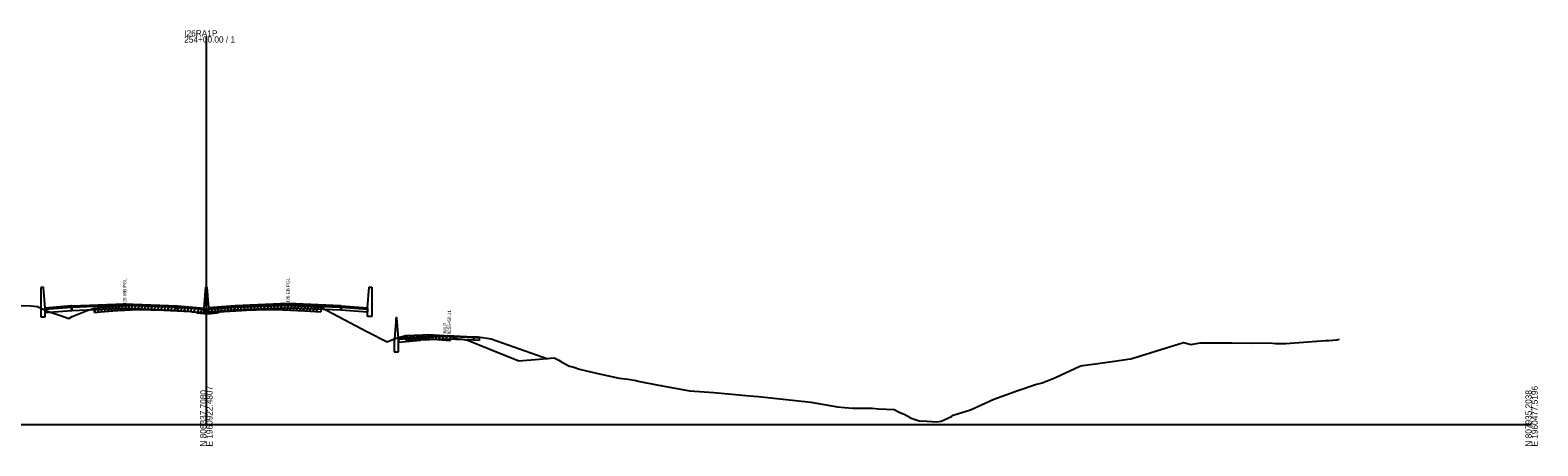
# Model space of a CAD drawing. Extents: x 1017 to 19997, y -1947 to 50737.
# Drawn here: x 10520 to 11203, y 3990 to 4179 of the extents above; entities that cross this region are included whole.
import ezdxf

# ---------------------------------------------------------------- set-up
doc = ezdxf.new("R2010")
doc.units = 0
for name, color, linetype in [('RD_GPK_XS_Cell', 7, 'Continuous'), ('RD_XS_Base', 7, 'Continuous'), ('RD_XS_ExGround', 7, 'Continuous'), ('RD_XS_ExPaveRet', 7, 'Continuous'), ('RD_XS_Greenside', 7, 'Continuous'), ('RD_XS_MedBWall', 7, 'Continuous'), ('RD_XS_Pave', 7, 'Continuous'), ('RD_XS_PaveOvlay', 7, 'Continuous'), ('RD_XS_TX_Notes', 7, 'Continuous')]:
    doc.layers.add(name, color=color, linetype=linetype)

msp = doc.modelspace()

# ---------------------------------------------------------------- linework, layer by layer
at = {"layer": 'RD_GPK_XS_Cell'}
for p, q in [((10600, 4000), (10600, 4175.88)), ((10000, 4000), (10600, 4000)), ((10600, 4000), (11200, 4000))]:
    msp.add_line(p, q, dxfattribs=at)
at = {"layer": 'RD_XS_Base'}
for points in [[(10539, 4053.04), (10527, 4052.08)], [(10527, 4052.08), (10527, 4050.74)], [(10527, 4050.74), (10539, 4051.7)], [(10539, 4051.7), (10539, 4053.04)], [(10539.05, 4051.71), (10539, 4051.7)], [(10539.05, 4053.05), (10539.05, 4051.71)], [(10539.05, 4051.71), (10563, 4052.68), (10587, 4051.71)], [(10587, 4051.71), (10587, 4053.05)], [(10599, 4052.11), (10587, 4053.05)], [(10587, 4051.71), (10599, 4050.77)], [(10599, 4050.77), (10599, 4052.11)], [(10601, 4050.88), (10601, 4052.22)], [(10613, 4051.82), (10601, 4050.88)], [(10613, 4051.82), (10613, 4053.16)], [(10660.95, 4051.83), (10637, 4052.79), (10613, 4051.82)], [(10660.95, 4051.83), (10660.95, 4053.17)], [(10661, 4051.82), (10660.95, 4051.83)], [(10661, 4053.16), (10661, 4051.82)], [(10661, 4053.16), (10673, 4052.2)], [(10661, 4051.82), (10661, 4053.16)], [(10673, 4050.86), (10661, 4051.82)], [(10673, 4052.2), (10673, 4050.86)], [(10697, 4039.48), (10687, 4038.68)], [(10687, 4038.68), (10687, 4037.34)], [(10687, 4037.34), (10697, 4038.14)], [(10697, 4039.48), (10709, 4039.96), (10721, 4039.48)], [(10697, 4038.14), (10697, 4039.48)], [(10721, 4038.16), (10709, 4038.62), (10697, 4038.14)], [(10721, 4039.48), (10721, 4038.16)], [(10721, 4039.48), (10723, 4039.4), (10723.5, 4039.38)], [(10723.5, 4038.04), (10721, 4038.16)], [(10723.5, 4039.38), (10723.5, 4038.04)]]:
    msp.add_lwpolyline(points, dxfattribs=at)
at = {"layer": 'RD_XS_ExGround'}
msp.add_lwpolyline([(10515.4, 4053.93), (10520.5, 4053.83), (10523.6, 4053.52), (10527.64, 4051.47), (10534.02, 4049.33), (10537.67, 4048.06), (10539.3, 4048.88), (10546.11, 4051.59), (10549.36, 4052.76), (10552.01, 4052.98), (10557.64, 4053.45), (10559.86, 4053.59), (10569.02, 4054.15), (10580.8, 4053.74), (10592.78, 4053.15), (10593.54, 4053.05), (10595.51, 4052.87), (10595.7, 4052.56), (10598.98, 4052.34), (10600, 4052.33), (10601.67, 4052.33), (10601.98, 4052.37), (10604.68, 4052.67), (10604.74, 4052.68), (10605.47, 4052.73), (10605.66, 4052.92), (10606.25, 4052.99), (10608.05, 4053.2), (10615.85, 4053.66), (10620.2, 4053.92), (10622.51, 4053.97), (10632.05, 4054.15), (10634.79, 4054.03), (10644.61, 4053.58), (10649.36, 4053.27), (10651.77, 4053.11), (10672.9, 4042), (10681.81, 4037.44), (10685.5, 4038.94), (10690.22, 4040.34), (10697.97, 4040.61), (10700.45, 4040.82), (10702.82, 4040.64), (10710.44, 4040.11), (10712.88, 4039.08), (10714.19, 4038.78), (10715.7, 4038.6), (10717.39, 4038.41), (10717.96, 4038.29), (10728.41, 4034.08), (10741.46, 4028.82), (10750.68, 4029.61), (10757.55, 4030.2), (10759.52, 4029.14), (10761.22, 4028.13), (10764.39, 4026.46), (10765.88, 4026.08), (10768.89, 4025.04), (10777.28, 4023.06), (10786.85, 4020.96), (10791.02, 4020.5), (10794.66, 4019.87), (10795.58, 4019.7), (10804.67, 4017.86), (10805.86, 4017.63), (10806.41, 4017.53), (10818.96, 4015.29), (10829.73, 4014.49), (10846.07, 4013.03), (10847.94, 4012.89), (10850, 4012.71), (10873.7, 4010.14), (10885.75, 4008.05), (10888.88, 4007.67), (10892.77, 4007.42), (10897.72, 4007.45), (10901.38, 4007.34), (10904.29, 4007.16), (10911.4, 4006.86), (10913.65, 4005.58), (10916.21, 4004.5), (10917.65, 4003.73), (10918.25, 4003.35), (10918.71, 4003.09), (10919.04, 4002.93), (10922.77, 4001.72), (10926.23, 4001.44), (10930.74, 4001.13), (10932.7, 4001.52), (10934.09, 4002.15), (10937.36, 4003.63), (10938.07, 4004.25), (10945.93, 4006.63), (10956.5, 4011.55), (10967.43, 4015.43), (10975.45, 4018.05), (10978.42, 4018.87), (10984.44, 4021.27), (10995.48, 4026.49), (10995.87, 4026.51), (10996.66, 4026.7), (11002.62, 4027.5), (11013.34, 4029.05), (11017.19, 4029.59), (11018.63, 4029.75), (11036.11, 4035.24), (11042.39, 4037.22), (11045.95, 4036.28), (11049.1, 4036.89), (11050.32, 4037.06), (11054.1, 4036.99), (11064.35, 4036.94), (11073.82, 4036.88), (11081.56, 4036.93), (11084.09, 4036.64), (11088.78, 4036.76), (11106.77, 4037.99), (11108.14, 4038.06), (11111.77, 4038.4), (11112.99, 4038.66)], dxfattribs=at)
at = {"layer": 'RD_XS_ExPaveRet'}
for p, q in [((10549.36, 4050.76), (10550.4, 4052.85)), ((10549.36, 4050.76), (10549.36, 4052.76)), ((10549.36, 4050.76), (10552.01, 4050.98)), ((10550.86, 4050.89), (10551.9, 4052.97)), ((10552.01, 4050.98), (10557.64, 4051.45)), ((10552.36, 4051.01), (10553.4, 4053.1)), ((10553.86, 4051.14), (10554.9, 4053.22)), ((10555.36, 4051.26), (10556.4, 4053.35)), ((10556.86, 4051.39), (10557.9, 4053.47)), ((10557.64, 4051.45), (10559.86, 4051.59)), ((10558.36, 4051.5), (10559.39, 4053.56)), ((10559.86, 4051.59), (10560.89, 4053.65)), ((10559.86, 4051.59), (10569.02, 4052.15)), ((10561.36, 4051.68), (10562.39, 4053.75)), ((10562.86, 4051.77), (10563.89, 4053.84)), ((10564.36, 4051.87), (10565.39, 4053.93)), ((10565.86, 4051.96), (10566.89, 4054.02)), ((10567.36, 4052.05), (10568.39, 4054.11)), ((10568.86, 4052.14), (10569.85, 4054.12)), ((10569.02, 4052.15), (10580.8, 4051.74)), ((10570.36, 4052.1), (10571.34, 4054.07)), ((10571.86, 4052.05), (10572.84, 4054.02)), ((10573.36, 4052), (10574.34, 4053.96)), ((10574.86, 4051.95), (10575.84, 4053.91)), ((10576.36, 4051.89), (10577.34, 4053.86)), ((10577.86, 4051.84), (10578.84, 4053.81)), ((10579.36, 4051.79), (10580.34, 4053.76)), ((10580.8, 4051.74), (10592.78, 4051.15)), ((10580.86, 4051.74), (10581.83, 4053.69)), ((10582.36, 4051.66), (10583.33, 4053.61)), ((10583.86, 4051.59), (10584.83, 4053.54)), ((10585.36, 4051.52), (10586.33, 4053.47)), ((10586.86, 4051.44), (10587.83, 4053.39)), ((10588.36, 4051.37), (10589.33, 4053.32)), ((10589.86, 4051.29), (10590.83, 4053.25)), ((10591.36, 4051.22), (10592.33, 4053.17)), ((10592.78, 4051.15), (10593.54, 4051.05)), ((10592.86, 4051.14), (10593.8, 4053.03)), ((10593.54, 4051.05), (10595.51, 4050.87)), ((10594.36, 4050.98), (10595.31, 4052.89)), ((10595.51, 4050.87), (10595.7, 4050.56)), ((10595.7, 4050.56), (10598.98, 4050.34)), ((10595.86, 4050.55), (10596.82, 4052.48)), ((10597.36, 4050.45), (10598.32, 4052.38)), ((10598.86, 4050.35), (10599.85, 4052.33)), ((10598.98, 4050.34), (10600, 4050.33)), ((10600, 4050.33), (10601.67, 4050.33)), ((10600.36, 4050.33), (10601.36, 4052.33)), ((10601.67, 4050.33), (10601.98, 4050.37)), ((10601.86, 4050.35), (10602.92, 4052.47)), ((10601.98, 4050.37), (10604.68, 4050.67)), ((10603.36, 4050.52), (10604.42, 4052.64)), ((10604.74, 4050.68), (10605.47, 4050.73)), ((10604.86, 4050.69), (10605.99, 4052.96)), ((10605.47, 4050.73), (10605.66, 4050.92)), ((10605.66, 4050.92), (10606.25, 4050.99)), ((10606.25, 4050.99), (10608.05, 4051.2)), ((10606.36, 4051), (10607.42, 4053.13)), ((10607.86, 4051.18), (10608.89, 4053.25)), ((10608.05, 4051.2), (10615.85, 4051.66)), ((10609.36, 4051.28), (10610.39, 4053.34)), ((10610.86, 4051.37), (10611.89, 4053.43)), ((10612.36, 4051.45), (10613.39, 4053.52)), ((10613.86, 4051.54), (10614.89, 4053.6)), ((10615.36, 4051.63), (10616.39, 4053.69)), ((10615.85, 4051.66), (10620.2, 4051.92)), ((10616.86, 4051.72), (10617.89, 4053.78)), ((10618.36, 4051.81), (10619.39, 4053.88)), ((10619.86, 4051.9), (10620.87, 4053.94)), ((10620.2, 4051.92), (10622.51, 4051.97)), ((10621.36, 4051.95), (10622.37, 4053.97)), ((10622.51, 4051.97), (10632.05, 4052.15)), ((10622.86, 4051.98), (10623.87, 4054)), ((10624.36, 4052.01), (10625.37, 4054.03)), ((10625.86, 4052.04), (10626.87, 4054.05)), ((10627.36, 4052.06), (10628.37, 4054.08)), ((10628.86, 4052.09), (10629.87, 4054.11)), ((10630.36, 4052.12), (10631.37, 4054.14)), ((10631.86, 4052.15), (10632.84, 4054.12)), ((10632.05, 4052.15), (10634.79, 4052.03)), ((10633.36, 4052.09), (10634.33, 4054.05)), ((10634.79, 4052.03), (10644.61, 4051.58)), ((10634.86, 4052.03), (10635.83, 4053.98)), ((10636.36, 4051.96), (10637.33, 4053.91)), ((10637.86, 4051.89), (10638.83, 4053.84)), ((10639.36, 4051.82), (10640.33, 4053.77)), ((10640.86, 4051.75), (10641.83, 4053.71)), ((10642.36, 4051.68), (10643.33, 4053.64)), ((10643.86, 4051.61), (10644.83, 4053.56)), ((10644.61, 4051.58), (10649.36, 4051.27)), ((10645.36, 4051.53), (10646.32, 4053.47)), ((10646.86, 4051.43), (10647.82, 4053.37)), ((10648.36, 4051.33), (10649.32, 4053.27)), ((10649.36, 4051.27), (10651.77, 4051.11)), ((10649.86, 4051.23), (10650.82, 4053.17)), ((10651.77, 4053.11), (10651.77, 4051.11)), ((10690.22, 4038.34), (10691.24, 4040.38)), ((10690.22, 4038.34), (10690.22, 4040.34)), ((10690.22, 4038.34), (10697.97, 4038.61)), ((10691.72, 4038.39), (10692.74, 4040.43)), ((10693.22, 4038.45), (10694.24, 4040.48)), ((10694.72, 4038.5), (10695.74, 4040.53)), ((10696.22, 4038.55), (10697.24, 4040.58)), ((10697.72, 4038.6), (10698.75, 4040.68)), ((10697.97, 4038.61), (10700.45, 4038.82)), ((10699.22, 4038.71), (10700.26, 4040.8)), ((10700.45, 4038.82), (10702.82, 4038.64)), ((10700.72, 4038.8), (10701.68, 4040.73)), ((10702.22, 4038.69), (10703.18, 4040.62)), ((10702.82, 4038.64), (10710.44, 4038.11)), ((10703.72, 4038.58), (10704.68, 4040.51)), ((10705.22, 4038.47), (10706.18, 4040.41)), ((10706.72, 4038.37), (10707.68, 4040.3)), ((10708.22, 4038.26), (10709.18, 4040.2)), ((10710.44, 4040.11), (10710.44, 4038.11))]:
    msp.add_line(p, q, dxfattribs=at)
at = {"layer": 'RD_XS_Greenside'}
for points in [[(10723, 4039.71), (10729, 4038.75)], [(10729, 4038.75), (10754.67, 4029.74)]]:
    msp.add_lwpolyline(points, dxfattribs=at)
at = {"layer": 'RD_XS_MedBWall'}
for points in [[(10527, 4052.76), (10526.25, 4062.1), (10525, 4062.1)], [(10525, 4062.1), (10525, 4048.76)], [(10599, 4052.76), (10599.75, 4062.22), (10600.25, 4062.22), (10601, 4052.88)], [(10673, 4052.88), (10673.75, 4062.22), (10675, 4062.22)], [(10675, 4062.22), (10675, 4048.88)], [(10525, 4048.76), (10527, 4048.76)], [(10527, 4048.76), (10527, 4052.76)], [(10599, 4050.76), (10599, 4052.76)], [(10601, 4050.76), (10599, 4050.76)], [(10601, 4052.88), (10601, 4050.76)], [(10673, 4048.88), (10673, 4052.88)], [(10675, 4048.88), (10673, 4048.88)], [(10687, 4038.99), (10686.25, 4048.33), (10685.75, 4048.33)], [(10685.75, 4048.33), (10685.75, 4046.33)], [(10685.75, 4046.33), (10685, 4036.99)], [(10685, 4036.99), (10685, 4032.99)], [(10687, 4032.99), (10687, 4038.99)], [(10685, 4032.99), (10687, 4032.99)]]:
    msp.add_lwpolyline(points, dxfattribs=at)
at = {"layer": 'RD_XS_Pave'}
for points in [[(10539, 4053.38), (10527, 4052.42)], [(10527, 4052.42), (10527, 4052.08)], [(10539, 4053.04), (10539, 4053.38)], [(10539.05, 4053.05), (10539, 4053.04)], [(10539.05, 4053.39), (10563, 4054.35), (10587, 4053.39)], [(10587, 4053.05), (10563, 4054.02), (10539.05, 4053.05)], [(10539.05, 4053.05), (10539.05, 4053.39)], [(10587, 4053.39), (10587, 4053.05)], [(10587, 4053.39), (10599, 4052.45)], [(10599, 4052.45), (10599, 4052.11)], [(10613, 4053.5), (10601, 4052.56)], [(10601, 4052.22), (10613, 4053.16)], [(10601, 4052.56), (10601, 4052.22)], [(10660.95, 4053.51), (10637, 4054.46), (10613, 4053.5)], [(10613, 4053.16), (10637, 4054.13), (10660.95, 4053.17)], [(10613, 4053.5), (10613, 4053.16)], [(10660.95, 4053.17), (10660.95, 4053.51)], [(10660.95, 4053.51), (10661, 4053.5)], [(10661, 4053.16), (10660.95, 4053.17)], [(10661, 4053.5), (10661, 4053.16)], [(10661, 4053.16), (10661, 4053.5)], [(10673, 4052.54), (10673, 4052.2)]]:
    msp.add_lwpolyline(points, dxfattribs=at)
at = {"layer": 'RD_XS_PaveOvlay'}
for points in [[(10660.95, 4053.84), (10637, 4054.8), (10613, 4053.84)], [(10539, 4053.72), (10527, 4052.76)], [(10527, 4052.76), (10527, 4052.42)], [(10539.05, 4053.73), (10539, 4053.72)], [(10539, 4053.72), (10539, 4053.38)], [(10539, 4053.38), (10539.05, 4053.39)], [(10539.05, 4053.73), (10563, 4054.68), (10587, 4053.72)], [(10539.05, 4053.39), (10539.05, 4053.73)], [(10587, 4053.72), (10587, 4053.39)], [(10587, 4053.72), (10599, 4052.76)], [(10599, 4052.76), (10599, 4052.45)], [(10613, 4053.84), (10601, 4052.88)], [(10601, 4052.88), (10601, 4052.56)], [(10613, 4053.84), (10613, 4053.5)], [(10660.95, 4053.51), (10660.95, 4053.84)], [(10660.95, 4053.84), (10661, 4053.84)], [(10661, 4053.84), (10661, 4053.5)], [(10661, 4053.84), (10673, 4052.88)], [(10661, 4053.5), (10661, 4053.84)], [(10673, 4052.54), (10661, 4053.5)], [(10673, 4052.88), (10673, 4052.54)], [(10697, 4039.79), (10687, 4038.99)], [(10687, 4038.68), (10697, 4039.48)], [(10687, 4038.99), (10687, 4038.68)], [(10697, 4039.79), (10709, 4040.27), (10721, 4039.79)], [(10721, 4039.48), (10709, 4039.96), (10697, 4039.48)], [(10697, 4039.48), (10697, 4039.79)], [(10721, 4039.79), (10721, 4039.48)], [(10721, 4039.79), (10723, 4039.71)], [(10723, 4039.4), (10721, 4039.48)], [(10723, 4039.71), (10723, 4039.4)]]:
    msp.add_lwpolyline(points, dxfattribs=at)

# ---------------------------------------------------------------- texts
at = {"layer": 'RD_GPK_XS_Cell'}
for s, p in [('I26RA1P', (10590, 4175.88)), ('254+00.00 / 1', (10590, 4173.08))]:
    msp.add_text(s, height=2.8, dxfattribs=at).set_placement(p)
for s, p in [('N 808337.7080', (10600, 3990)), ('E 1960922.4807', (10602.8, 3990)), ('N 807935.2038', (11200, 3990)), ('E 1960477.5196', (11202.8, 3990))]:
    msp.add_text(s, height=2.8, rotation=90, dxfattribs=at).set_placement(p)
at = {"layer": 'RD_XS_TX_Notes'}
for s, p in [('I26 WB PGL', (10563.75, 4054.68)), ('I26 EB PGL', (10637.75, 4055.53)), (' 9255+56.11', (10710.73, 4040.25)), (' JMLP', (10708.77, 4040.25))]:
    msp.add_text(s, height=1.5, rotation=90, dxfattribs=at).set_placement(p)

doc.saveas('drawing.dxf')
